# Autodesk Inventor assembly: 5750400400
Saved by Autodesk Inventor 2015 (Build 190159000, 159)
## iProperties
Created: 2020-07
Part Number: 5750400400
Checked By: TraceParts S.A.
Catalog Web Link: www.traceparts.com
Document SubType Name: Assembly
Designer: TraceParts
Company: TraceParts S.A.
Author: TraceParts
REFERENCE: 5750400400
DESIGN: HXBR-450 ECOWATT (230V50/60HZ) V5 - 5750400400
SUPPLIER: Soler & Palau
TraceParts.PartNumber: 10-20122018-119605
TraceParts.PartTitle: HXBR-ECOWATT
TraceParts.InstanceId: 10-20122018-11960556PAY4J5BJB2NPDORKO5PIOM2
TraceParts.PartStatus: Published
TraceParts.PartVersion: 1.0.2
TRACEPARTS: TRACEPARTS
TraceParts.PartLanguage: en
TraceParts.ClassPath: SOLER_PALAU:10-20122018-119605
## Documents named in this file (3)
- C:\TPO v2\SharedFS\Outgoing\5750400400.iam
- C:\TPO v2\SharedFS\Outgoing\5750400400_01.ipt
- C:\TPO v2\SharedFS\Outgoing\5750400400_02.ipt
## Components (2 placed, 2 different names)
1. 5750400400_01:1
2. 5750400400_02:1
